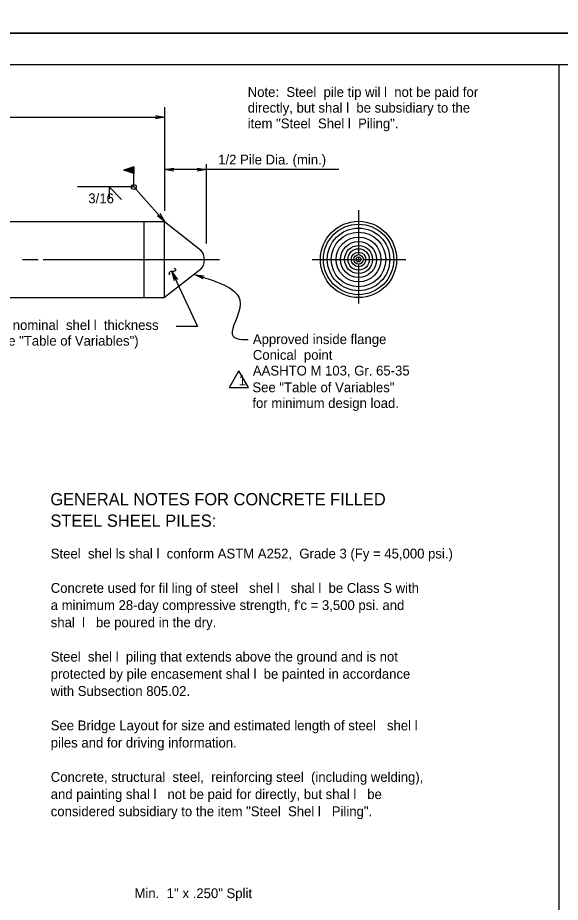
# Model space of a CAD drawing. Extents: x 1053 to 1311, y 5085 to 5337.
# Drawn here: x 1127 to 1163.9, y 5139.9 to 5199.9 of the extents above; entities that cross this region are included whole.
import ezdxf

# ---------------------------------------------------------------- set-up
doc = ezdxf.new("R2010")
doc.units = 0
for name, color, linetype in [('1', 7, 'Continuous'), ('7', 7, 'Continuous'), ('B_Dimension', 7, 'Continuous'), ('B_No_Plot', 7, 'Continuous')]:
    doc.layers.add(name, color=color, linetype=linetype)

msp = doc.modelspace()

# ---------------------------------------------------------------- linework, layer by layer
at = {"layer": '1'}
for p, q in [((1060.921, 5196.747), (1229.529, 5196.747)), ((1136.995, 5193.832), (1136.995, 5186.801)), ((1087.04, 5193.165), (1136.995, 5193.165)), ((1134.901, 5189.786), (1134.218, 5189.563)), ((1134.901, 5189.341), (1134.218, 5189.563)), ((1134.261, 5189.549), (1134.24, 5189.57)), ((1134.254, 5189.552), (1134.288, 5189.586)), ((1134.376, 5189.512), (1134.298, 5189.59)), ((1134.312, 5189.533), (1134.404, 5189.624)), ((1134.492, 5189.474), (1134.357, 5189.609)), ((1134.371, 5189.513), (1134.519, 5189.661)), ((1134.607, 5189.437), (1134.416, 5189.628)), ((1134.43, 5189.494), (1134.634, 5189.699)), ((1134.722, 5189.399), (1134.474, 5189.647)), ((1134.488, 5189.475), (1134.75, 5189.736)), ((1134.837, 5189.362), (1134.533, 5189.666)), ((1134.547, 5189.456), (1134.865, 5189.774)), ((1134.901, 5189.376), (1134.592, 5189.685)), ((1134.606, 5189.437), (1134.901, 5189.732)), ((1134.901, 5189.454), (1134.651, 5189.704)), ((1134.664, 5189.418), (1134.901, 5189.654)), ((1134.901, 5189.532), (1134.709, 5189.723)), ((1134.723, 5189.399), (1134.901, 5189.577)), ((1134.901, 5189.609), (1134.768, 5189.742)), ((1134.782, 5189.38), (1134.901, 5189.499)), ((1134.901, 5189.687), (1134.827, 5189.761)), ((1134.901, 5189.765), (1134.885, 5189.781)), ((1134.901, 5188.422), (1134.901, 5189.786)), ((1139.817, 5189.601), (1136.995, 5189.601)), ((1139.817, 5189.978), (1139.817, 5184.586)), ((1148.828, 5189.601), (1139.817, 5189.601)), ((1134.841, 5189.361), (1134.901, 5189.421)), ((1134.899, 5189.342), (1134.901, 5189.343)), ((1134.901, 5188.422), (1131.078, 5188.422)), ((1133.231, 5188.422), (1133.231, 5187.615)), ((1134.069, 5187.583), (1133.231, 5188.422)), ((1134.901, 5188.422), (1136.995, 5186.086)), ((1150.174, 5186.838), (1150.174, 5183.795)), ((1121.763, 5186.086), (1136.995, 5186.086)), ((1135.602, 5180.907), (1135.602, 5186.086)), ((1136.995, 5180.907), (1136.995, 5186.086)), ((1136.995, 5186.086), (1139.441, 5184.157)), ((1127.335, 5183.496), (1128.391, 5183.496)), ((1128.731, 5183.496), (1140.727, 5183.496)), ((1147.015, 5183.502), (1150.174, 5183.502)), ((1150.004, 5183.502), (1150.335, 5183.502)), ((1150.174, 5183.67), (1150.174, 5183.352)), ((1150.511, 5183.502), (1153.376, 5183.502)), ((1150.174, 5183.236), (1150.174, 5180.516)), ((1139.429, 5182.815), (1136.995, 5180.907)), ((1137.519, 5182.646), (1139.222, 5178.949)), ((1121.763, 5180.907), (1136.995, 5180.907)), ((1139.222, 5178.949), (1137.769, 5178.949)), ((1141.395, 5174.81), (1142.046, 5175.937)), ((1142.696, 5174.81), (1142.046, 5175.937)), ((1141.395, 5174.81), (1142.696, 5174.81))]:
    msp.add_line(p, q, dxfattribs=at)
for points in [[(1136.38, 5193.274), (1136.995, 5193.165), (1136.38, 5193.057)], [(1137.611, 5189.492), (1136.995, 5189.601), (1137.611, 5189.709)], [(1139.202, 5189.709), (1139.817, 5189.601), (1139.202, 5189.492)], [(1139.626, 5182.187), (1139.067, 5182.465), (1139.688, 5182.395)]]:
    msp.add_lwpolyline(points, dxfattribs=at)
msp.add_lwpolyline([(1134.901, 5189.341), (1134.218, 5189.563), (1134.901, 5189.786)], close=True, dxfattribs=at)
for centre, radius in [((1134.901, 5188.422), 0.167), ((1150.174, 5183.502), 2.589), ((1150.174, 5183.502), 2.392), ((1150.174, 5183.502), 2.124), ((1150.174, 5183.502), 1.852), ((1150.174, 5183.502), 1.523), ((1150.174, 5183.502), 1.222), ((1150.174, 5183.502), 0.95), ((1150.174, 5183.502), 0.728), ((1150.174, 5183.502), 0.496), ((1150.174, 5183.502), 0.325), ((1150.174, 5183.502), 0.167)]:
    msp.add_circle(centre, radius, dxfattribs=at)
msp.add_arc((1138.749, 5183.493), 0.959, 314.33668, 43.87438, dxfattribs=at)
msp.add_spline([(1137.356, 5182.432), (1137.315, 5182.577), (1137.335, 5182.618), (1137.397, 5182.68), (1137.48, 5182.701), (1137.563, 5182.701), (1137.666, 5182.721), (1137.707, 5182.742), (1137.749, 5182.784), (1137.749, 5182.825), (1137.707, 5182.866), (1137.645, 5182.908)], degree=3, dxfattribs=at)
at = {"layer": '7'}
msp.add_line((1163.789, 5196.747), (1163.789, 5087.179), dxfattribs=at)
msp.add_open_spline([(1139.067, 5182.465), (1140.935, 5181.914), (1142.916, 5181.01), (1140.985, 5178.157), (1142.087, 5178.031), (1142.679, 5178.071)], degree=3, dxfattribs=at)
at = {"layer": 'B_Dimension'}
for points in [[(1136.665, 5186.616), (1136.995, 5186.086), (1136.504, 5186.472)], [(1137.678, 5182.041), (1137.519, 5182.646), (1137.875, 5182.132)]]:
    msp.add_lwpolyline(points, dxfattribs=at)
at = {"layer": 'B_No_Plot'}
for points in [[(1053.308, 5312.654), (1231.974, 5312.654), (1231.974, 5198.862), (1053.308, 5198.862)], [(1053.308, 5198.862), (1231.974, 5198.862), (1231.974, 5085.07), (1053.308, 5085.07)]]:
    msp.add_lwpolyline(points, close=True, dxfattribs=at)

# ---------------------------------------------------------------- texts
at = {"layer": '1'}
for s, height, p in [('Note:  Steel  pile tip wil l  not be paid for ', 0.66667, (1142.642, 5194.536)), ('directly, but shal l  be subsidiary to the ', 0.66667, (1142.642, 5193.469)), ('item "Steel  Shel l  Piling".', 0.66667, (1142.642, 5192.403)), ('1/2 Pile Dia. (min.)', 0.66667, (1140.636, 5189.95)), ('3/16', 0.6667, (1131.812, 5187.315)), ("''T'' = nominal  shel l  thickness", 0.66667, (1124.434, 5178.715)), ('(See "Table of Variables")', 0.66667, (1124.98, 5177.648)), ('Approved inside flange', 0.66667, (1142.993, 5177.755)), ('Conical  point', 0.66667, (1142.993, 5176.688)), ('AASHTO M 103, Gr. 65-35', 0.66667, (1142.993, 5175.622)), ('1', 0.667, (1142.029, 5174.957)), ('See "Table of Variables"', 0.66666, (1142.961, 5174.485)), ('for minimum design load.', 0.66666, (1142.961, 5173.418)), ('Steel  shel ls shal l  conform ASTM A252,  Grade 3 (Fy = 45,000 psi.)', 0.66667, (1129.257, 5163.198)), ('Concrete used for fil ling of steel   shel l   shal l  be Class S with', 0.66667, (1129.257, 5160.864)), ("a minimum 28-day compressive strength, f'c = 3,500 psi. and ", 0.66667, (1129.257, 5159.698)), ('shal  l   be poured in the dry.', 0.66667, (1129.257, 5158.531)), ('Steel  shel l  piling that extends above the ground and is not ', 0.66667, (1129.257, 5156.198)), ('protected by pile encasement shal l  be painted in accordance ', 0.66667, (1129.257, 5155.031)), ('with Subsection 805.02.', 0.66667, (1129.257, 5153.864)), ('See Bridge Layout for size and estimated length of steel   shel l   ', 0.66667, (1129.257, 5151.531)), ('piles and for driving information.', 0.66667, (1129.257, 5150.364)), ('Concrete, structural  steel,  reinforcing steel  (including welding),  ', 0.66667, (1129.257, 5148.031)), ('and painting shal l   not be paid for directly, but shal l   be ', 0.66667, (1129.257, 5146.864)), ('considered subsidiary to the item "Steel  Shel l   Piling".', 0.66667, (1129.257, 5145.698)), ('Min.  1\'\' x .250" Split', 0.66658, (1134.947, 5140.136))]:
    msp.add_text(s, height=height, dxfattribs=at).set_placement(p)
at = {"layer": '7'}
for s, p in [('GENERAL NOTES FOR CONCRETE FILLED', (1129.233, 5166.807)), ('STEEL SHEEL PILES:', (1129.233, 5165.349))]:
    msp.add_text(s, height=0.83333, dxfattribs=at).set_placement(p)

doc.saveas('drawing.dxf')
